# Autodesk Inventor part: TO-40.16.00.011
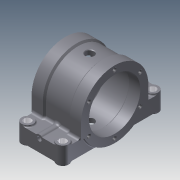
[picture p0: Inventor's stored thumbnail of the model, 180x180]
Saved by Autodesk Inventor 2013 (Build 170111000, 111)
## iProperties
Shininess: 25.0
Length Units: 11269
Angle Units: 11279
Time Units: 11290
Mass Units: 11283
Length Display Precision: 3
Angle Display Precision: 2
Created: 2001-08
Part Number: TO-40.16.00.011
Document SubType Name: Modeling
Designer: SOleg
Density: 1 g/cm^3
Material: Generic
Mass: 2403.54 g
Surface Area: 3195.95 cm^2
Volume: 2403.54 cm^3
Density: 0.0
Volumn: 0.0
Area: 0.0
PropertySet Name: Model Information
Control State: 0
Master: False
Checked Out: True
Checked Out Date: 2008-10-15
Last Check In Date: 2008-10-15
Author: SOleg
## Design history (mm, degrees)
feature "Base1"
thread "Thread1" dims "d0" = 10, "d1" = 0
thread "Thread2" dims "d2" = 10, "d3" = 0
thread "Thread3" dims "d4" = 10, "d5" = 0
thread "Thread4" dims "d6" = 10, "d7" = 0
thread "Thread5" dims "d8" = 10, "d9" = 0
thread "Thread6" dims "d10" = 10, "d11" = 0
thread "Thread7" dims "d12" = 10, "d13" = 0
thread "Thread8" dims "d14" = 10, "d15" = 0
thread "Thread9" dims "d16" = 10, "d17" = 0
thread "Thread10" dims "d18" = 10, "d19" = 0
thread "Thread11" dims "d20" = 10, "d21" = 0
thread "Thread12" dims "d22" = 10, "d23" = 0
body "Solid1"
